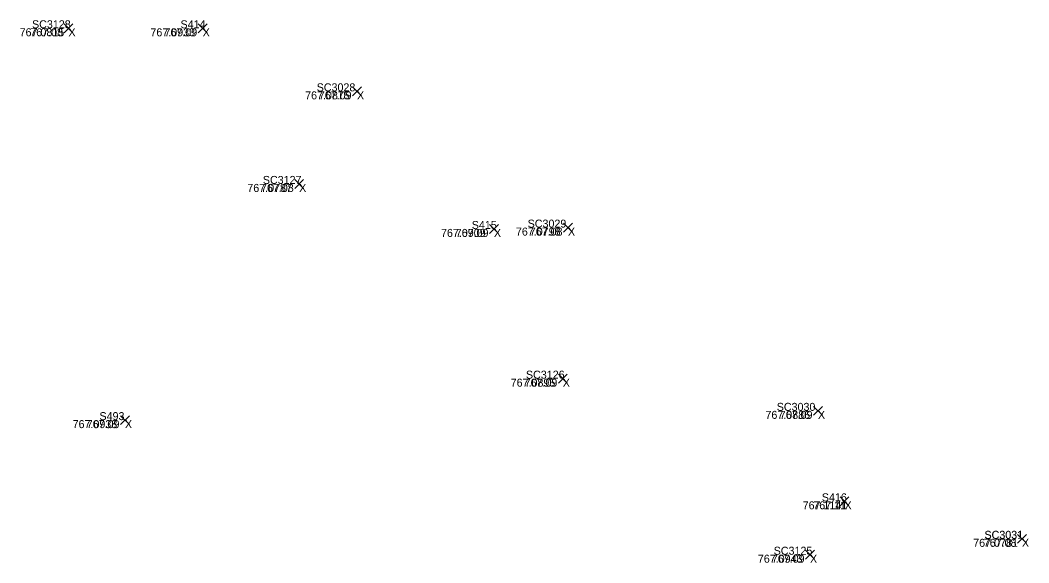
# Model space of a CAD drawing. Extents: x 1845019 to 1877956, y 680444 to 701081.
# Drawn here: x 1857746.39 to 1857753.96, y 694238.27 to 694242.35 of the extents above; entities that cross this region are included whole.
import ezdxf

# ---------------------------------------------------------------- set-up
doc = ezdxf.new("R2010")
doc.units = 0
for name, color, linetype in [('SV_X_Random_Point', 7, 'Continuous'), ('SV_X_Text_Comment', 7, 'Continuous'), ('SV_X_Text_Elevation', 7, 'Continuous'), ('SV_X_Text_Name', 7, 'Continuous')]:
    doc.layers.add(name, color=color, linetype=linetype)

msp = doc.modelspace()

# ---------------------------------------------------------------- linework, layer by layer
at = {"layer": 'SV_X_Random_Point'}
for p, q in [((1857746.7232, 694242.252), (1857746.7898, 694242.3188)), ((1857746.7232, 694242.3188), (1857746.7898, 694242.252)), ((1857746.7232, 694242.252), (1857746.7898, 694242.3188)), ((1857746.7232, 694242.3188), (1857746.7898, 694242.252)), ((1857747.7295, 694242.2517), (1857747.7961, 694242.3185)), ((1857747.7295, 694242.3185), (1857747.7961, 694242.2517)), ((1857747.7295, 694242.2517), (1857747.7961, 694242.3185)), ((1857747.7295, 694242.3185), (1857747.7961, 694242.2517)), ((1857748.8869, 694241.7787), (1857748.9535, 694241.8455)), ((1857748.8869, 694241.8455), (1857748.9535, 694241.7787)), ((1857748.8869, 694241.7787), (1857748.9535, 694241.8455)), ((1857748.8869, 694241.8455), (1857748.9535, 694241.7787)), ((1857748.4533, 694241.0839), (1857748.5199, 694241.1507)), ((1857748.4533, 694241.1507), (1857748.5199, 694241.0839)), ((1857748.4533, 694241.0839), (1857748.5199, 694241.1507)), ((1857748.4533, 694241.1507), (1857748.5199, 694241.0839)), ((1857749.9137, 694240.7461), (1857749.9803, 694240.8129)), ((1857749.9137, 694240.8129), (1857749.9803, 694240.7461)), ((1857749.9137, 694240.7461), (1857749.9803, 694240.8129)), ((1857749.9137, 694240.8129), (1857749.9803, 694240.7461)), ((1857750.4689, 694240.7562), (1857750.5355, 694240.823)), ((1857750.4689, 694240.823), (1857750.5355, 694240.7562)), ((1857750.4689, 694240.7562), (1857750.5355, 694240.823)), ((1857750.4689, 694240.823), (1857750.5355, 694240.7562)), ((1857750.4301, 694239.6225), (1857750.4967, 694239.6893)), ((1857750.4301, 694239.6893), (1857750.4967, 694239.6225)), ((1857750.4301, 694239.6225), (1857750.4967, 694239.6893)), ((1857750.4301, 694239.6893), (1857750.4967, 694239.6225)), ((1857752.3434, 694239.3809), (1857752.41, 694239.4477)), ((1857752.3434, 694239.4477), (1857752.41, 694239.3809)), ((1857752.3434, 694239.3809), (1857752.41, 694239.4477)), ((1857752.3434, 694239.4477), (1857752.41, 694239.3809)), ((1857747.1467, 694239.3114), (1857747.2133, 694239.3782)), ((1857747.1467, 694239.3782), (1857747.2133, 694239.3114)), ((1857747.1467, 694239.3114), (1857747.2133, 694239.3782)), ((1857747.1467, 694239.3782), (1857747.2133, 694239.3114)), ((1857752.5426, 694238.7021), (1857752.6092, 694238.7689)), ((1857752.5426, 694238.7689), (1857752.6092, 694238.7021)), ((1857752.5426, 694238.7021), (1857752.6092, 694238.7689)), ((1857752.5426, 694238.7689), (1857752.6092, 694238.7021)), ((1857753.873, 694238.4207), (1857753.9396, 694238.4875)), ((1857753.873, 694238.4875), (1857753.9396, 694238.4207)), ((1857753.873, 694238.4207), (1857753.9396, 694238.4875)), ((1857753.873, 694238.4875), (1857753.9396, 694238.4207)), ((1857752.284, 694238.3013), (1857752.3506, 694238.3681)), ((1857752.284, 694238.3681), (1857752.3506, 694238.3013)), ((1857752.284, 694238.3013), (1857752.3506, 694238.3681)), ((1857752.284, 694238.3681), (1857752.3506, 694238.3013))]:
    msp.add_line(p, q, dxfattribs=at)

# ---------------------------------------------------------------- texts
at = {"layer": 'SV_X_Text_Comment'}
for p in [(1857746.7565, 694242.2254), (1857747.7628, 694242.2251), (1857748.9202, 694241.7521), (1857748.4866, 694241.0573), (1857749.947, 694240.7195), (1857750.5022, 694240.7296), (1857750.4634, 694239.5959), (1857752.3767, 694239.3543), (1857747.18, 694239.2848), (1857752.5759, 694238.6755), (1857753.9063, 694238.3941), (1857752.3173, 694238.2747)]:
    msp.add_text('X', height=0.06, dxfattribs=at).set_placement(p)
at = {"layer": 'SV_X_Text_Elevation'}
for s, p in [('767.0815', (1857746.3904, 694242.2254)), ('767.08', (1857746.4702, 694242.2254)), ('767.0933', (1857747.3712, 694242.2251)), ('767.09', (1857747.4765, 694242.2251)), ('767.0875', (1857748.5314, 694241.7521)), ('767.09', (1857748.6339, 694241.7521)), ('767.0787', (1857748.0978, 694241.0573)), ('767.08', (1857748.2003, 694241.0573)), ('767.0909', (1857749.5502, 694240.7195)), ('767.09', (1857749.6607, 694240.7195)), ('767.0798', (1857750.112, 694240.7296)), ('767.08', (1857750.2159, 694240.7296)), ('767.0895', (1857750.0727, 694239.5959)), ('767.09', (1857750.1771, 694239.5959)), ('767.0886', (1857751.9832, 694239.3543)), ('767.09', (1857752.0904, 694239.3543)), ('767.0938', (1857746.7879, 694239.2848)), ('767.09', (1857746.8937, 694239.2848)), ('767.1141', (1857752.2621, 694238.6755)), ('767.11', (1857752.342, 694238.6755)), ('767.0781', (1857753.541, 694238.3941)), ('767.08', (1857753.62, 694238.3941)), ('767.0943', (1857751.9262, 694238.2747)), ('767.09', (1857752.031, 694238.2747))]:
    msp.add_text(s, height=0.06, dxfattribs=at).set_placement(p)
at = {"layer": 'SV_X_Text_Name'}
for s, p in [('SC3128', (1857746.4835, 694242.2854)), ('SC3128', (1857746.4835, 694242.2854)), ('S414', (1857747.597, 694242.2851)), ('S414', (1857747.597, 694242.2851)), ('SC3028', (1857748.6179, 694241.8121)), ('SC3028', (1857748.6179, 694241.8121)), ('SC3127', (1857748.2141, 694241.1173)), ('SC3127', (1857748.2141, 694241.1173)), ('S415', (1857749.7807, 694240.7795)), ('S415', (1857749.7807, 694240.7795)), ('SC3029', (1857750.1999, 694240.7896)), ('SC3029', (1857750.1999, 694240.7896)), ('SC3126', (1857750.1871, 694239.6559)), ('SC3126', (1857750.1871, 694239.6559)), ('SC3030', (1857752.0677, 694239.4143)), ('SC3030', (1857752.0677, 694239.4143)), ('S493', (1857746.9892, 694239.3448)), ('S493', (1857746.9892, 694239.3448)), ('S416', (1857752.4059, 694238.7355)), ('S416', (1857752.4059, 694238.7355)), ('SC3031', (1857753.6251, 694238.4541)), ('SC3031', (1857753.626, 694238.4541)), ('SC3125', (1857752.0448, 694238.3347)), ('SC3125', (1857752.0448, 694238.3347))]:
    msp.add_text(s, height=0.06, dxfattribs=at).set_placement(p)

doc.saveas('drawing.dxf')
